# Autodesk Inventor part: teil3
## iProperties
Created: 2005-10
Part Number: teil3
Document SubType Name: Modeling
Designer: Bernhard Fetzer
Author: Bernhard Fetzer
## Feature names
1. Extrusion1
2. Fase1 [Chamfer]
3. Extrusion2
4. Extrusion3
5. Rundung1 [Fillet]
